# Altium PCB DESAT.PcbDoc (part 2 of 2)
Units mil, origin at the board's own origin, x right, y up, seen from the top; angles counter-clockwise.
Board outline 3543.31 x 1895 mil, 4 copper layers (Top Layer, Signal Layer 1, Signal Layer 2, Bottom Layer), stack 40 mil thick; 82 components, 118 nets, 154 pads, 24 vias.
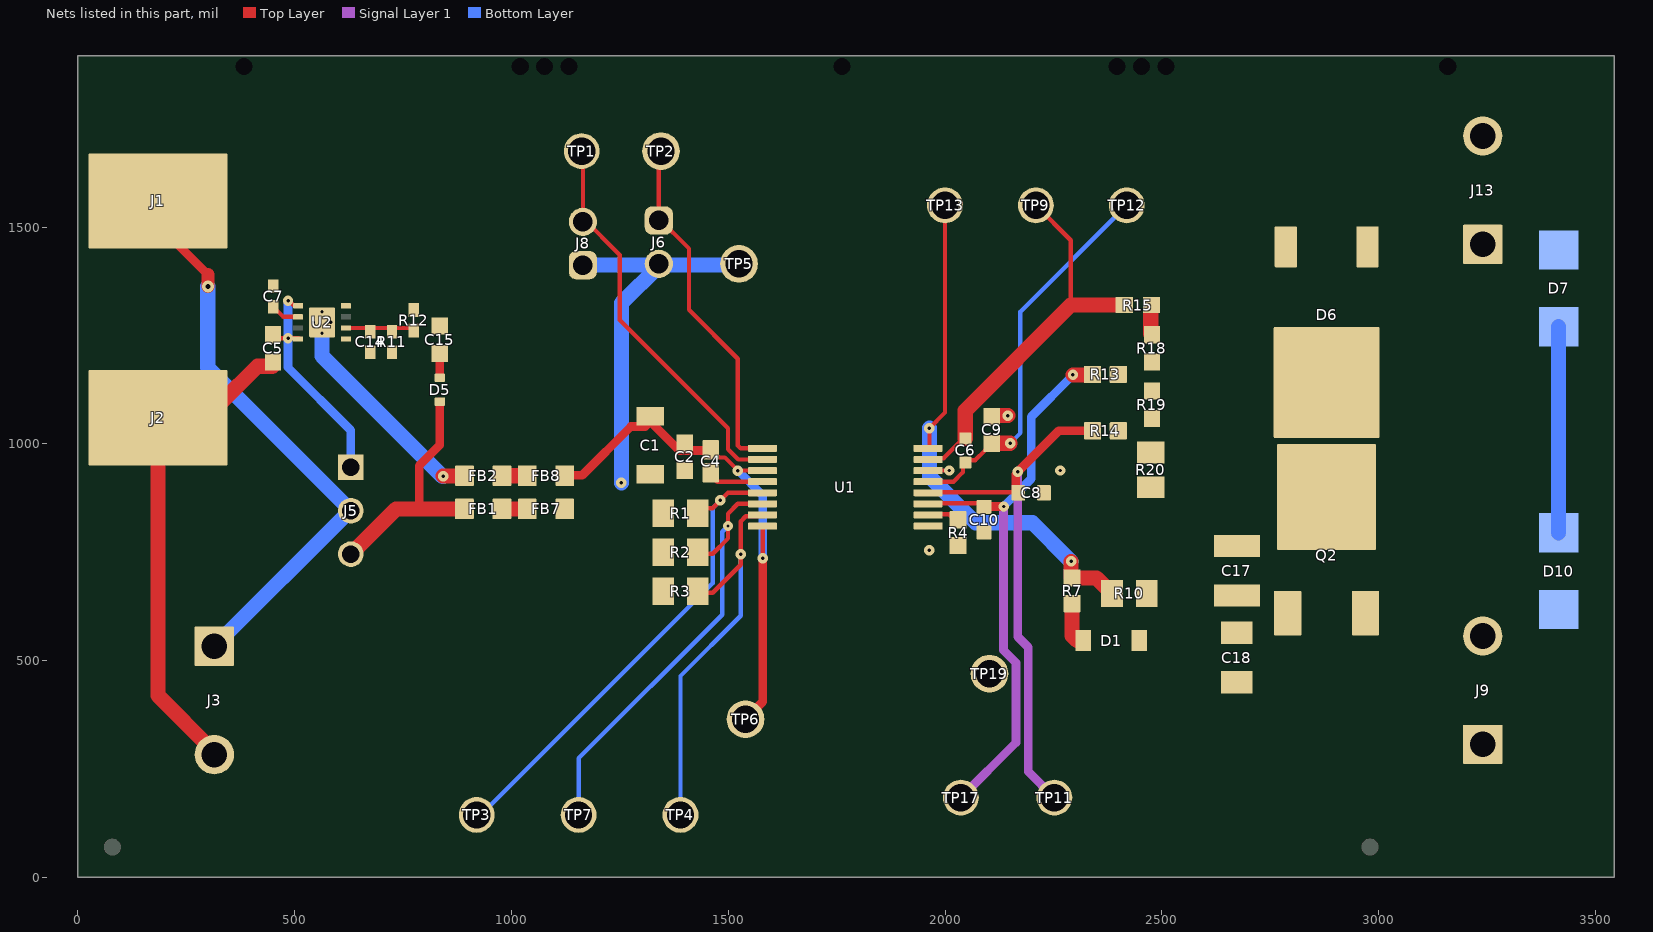
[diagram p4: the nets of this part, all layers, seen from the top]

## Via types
v1: diameter 24, hole 8, Top Layer to Bottom Layer, tented both sides, 19 vias
v2: diameter 19.68, hole 7.87, Top Layer to Bottom Layer, 4 vias
v3: diameter 27.56, hole 11.81, Top Layer to Bottom Layer, tented both sides, 1 vias

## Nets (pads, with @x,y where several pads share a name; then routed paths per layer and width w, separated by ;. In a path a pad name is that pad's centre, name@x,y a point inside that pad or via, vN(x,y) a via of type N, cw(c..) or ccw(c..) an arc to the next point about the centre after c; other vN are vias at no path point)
1ALM1_CMP: 
1CE: 
1EN: 
1FLT1_CMP: 
1HV+: 
1LDO_IN+: 
1LDO_OUT: 
1nALM1: 
1nFLT1: 
1PGOOD: 
1RESP: 
1VDDH: 
1VDDM: 
1VDDP: 
1VDDP_filtered: 
1VDRV: 
1VGATE: 
1VSSP: 
1VSSP_filtered: 
1VSSS: 
2CE: 
2EN: 
2FLT1_CMP: 
2FLT2_CMP: 
2HV+: 
2HV-: 
2LDO_IN+: 
2LDO_OUT: 
2nFLT1: 
2nFLT2: 
2PGOOD: 
2RESP: 
2VDDH: 
2VDDM: 
2VDDP: 
2VDDP_filtered: 
2VDRV: 
2VGATE1: 
2VGATE2: 
2VSSP: 
2VSSP_filtered: 
2VSSS: 
3ALM1_CMP: 
3CE: 
3EN: 
3FLT1_CMP: 
3HV+: 
3IN+: 
3LDO_IN+: 
3LDO_OUT: 
3nALM1: 
3nFLT1: 
3PGOOD: 
3RESP: 
3VDDH: 
3VDDM: 
3VDDP: 
3VDDP_filtered: 
3VDRV: 
3VGATE: 
3VSSP: 
3VSSP_filtered: 
3VSSS: 
4ALM1_CMP: C10.2 R13.1 TP17.1 U1.11 | length 1338.9
  Top Layer w10: U1.11@1951.57,862.87 2083.26,862.87 C10.2@2090.62,855.51
  Top Layer w20: C10.2@2090,854.53 2090.98,855.51 v1(2134.98,855.51)
  Top Layer w35: v1(2295.06,1158.98) 2339.23,1158.98 R13.1@2340.28,1160.02
  Signal Layer 1 w20: TP17.1@2036.59,184.16 2163.87,311.45 2163.87,495.42 2134.98,524.31 v1(2134.98,855.51)
  Bottom Layer w20: v1(2134.98,855.51) 2198.68,919.2 2198.68,1062.59 v1(2295.06,1158.98)
4CE: J8.2 TP1.1 U1.2 | length 928
  Top Layer w10: TP1.1@1165,1687.75 1165,1520.54 1250,1435.54 1250,1285.7 1499.54,1036.16 1499.54,987.64 1523.2,963.98 U1.2@1579.06,963.98
4EN: J6.1 TP2.1 U1.1 | length 828.6
  Top Layer w10: TP2.1@1340,1689.72 1340,1519.72 1409.46,1450.26 1409.46,1309.07 1522.17,1196.36 1522.17,996.26 1528.86,989.57 U1.1@1579.06,989.57
4FLT1_CMP: C8.2 R14.1 TP11.1 U1.12 | length 1258.8
  Top Layer w10: U1.12@1951.57,888.46 C8.2@2159.55,888.46
  Top Layer w20: C8.2@2169.15,886.99 2163.4,892.73 2163.4,930.14 2167.79,934.54 v1(2167.79,935.62) 2262.17,1030 R14.1@2340.28,1030
  Signal Layer 1 w20: v1(2167.79,935.62) 2167.79,554.87 2191.74,530.92 2191.74,244.52 TP11.1@2252.1,184.16
4HV+: D6.1 D7.1 J13.1 J13.2
4LDO_IN+: C5.1 J5.1 U2.5 U2.8 | length 532
  Top Layer w10: C5.1@449.96,1244.2 450.62,1243.54 v1(485,1243.54) U2.8@509.76,1243.54 ; v1(485,1329.72) 487.62,1329.72 497.86,1319.49 507.16,1319.49 U2.5@508.26,1318.39
  Bottom Layer w20: v1(485,1329.72) 485,1176.29 629.87,1031.42 J5.1@629.87,945.72
4LDO_OUT: C14.1 C15.1 D5.2 R11.2 U2.1 | length 57.2
  Top Layer w20: D5.2@835,1152.34 C15.1@835,1208.5 C15.1@835.72,1207.78
4nALM1: R3.2 TP4.1 U1.7 | length 956.5
  Top Layer w10: R3.2@1430,654.72 1431.78,656.5 1464.14,656.5 1528.86,721.22 v1(1528.86,745.72) 1528.86,821.14 1540.67,832.95 1581.29,832.95 U1.7@1584.36,836.02
  Bottom Layer w10: TP4.1@1390,134.72 1390,464.72 1528.86,603.58 v1(1528.86,745.72)
4nFLT1: R2.2 TP7.1 U1.6 | length 1054.6
  Top Layer w10: R2.2@1430,744.72 1431.92,746.65 1464.14,746.65 1499.54,782.04 v1(1499.54,810.51) 1499.54,838.98 1522.17,861.61 U1.6@1584.36,861.61
  Bottom Layer w10: TP7.1@1155,134.72 1155,274.72 1486.17,605.9 1486.17,797.15 v1(1499.54,810.51)
4PGOOD: R1.2 TP3.1 U1.5 | length 1143.6
  Top Layer w10: R1.2@1430,834.72 1447.09,851.81 1464.14,851.81 v1(1481.84,869.51) 1499.54,887.2 U1.5@1584.36,887.2
  Bottom Layer w10: TP3.1@920,134.72 1464,678.72 1464,851.67 v1(1481.84,869.51)
4RESP: R4.1 U1.10 | length 88
  Top Layer w10: U1.10@1951.57,837.28 2009.05,837.28 R4.1@2030.62,815.71
4VDDH: C6.1 R15.2 TP9.1 U1.15 | length 899.2
  Top Layer w10: U1.15@1960.95,963.98 1964.02,967.05 1997.03,967.05 2033.48,1003.5 2038.01,1003.5 C6.1@2046.79,1012.28 ; TP9.1@2209.59,1550 2289.92,1469.67 2289.92,1320
  Top Layer w35: C6.1@2046.79,1012.28 2046.79,1076.88 2289.92,1320 R15.2@2411.58,1320
4VDDM: C6.2 C9.2 TP12.1 U1.13 | length 895.8
  Top Layer w10: U1.13@1960.95,912.8 2019.51,912.8 2041.51,934.8 2041.51,951.87 2051.84,962.21 2069.38,962.21 2093.03,985.85 2094.02,985.85 C9.2@2107.72,999.55
  Top Layer w35: C9.2@2107.72,999.55 2109.66,1001.5 v1(2150,1001.5)
  Bottom Layer w10: v1(2150,1001.5) 2173.79,1025.29 2173.79,1304.62 TP12.1@2419.17,1550
4VDDP: D5.1 FB1.1 J5.3 | length 577.1
  Top Layer w20: 775,850 787.5,862.5 787.5,949.81 835,997.31 D5.1@835,1097.22
  Top Layer w35: J5.3@629.87,745.72 734.15,850 775,850 787.5,850 FB1.1@891.69,850
4VDDP_filtered: C1.1 C2.1 C4.2 FB7.2 J6.2 J8.1 R1.1 R2.1 R3.1 TP5.1 U1.4 | length 1008
  Top Layer w10: C4.2@1460,927.37 1474.58,912.79 U1.4@1579.06,912.8
  Bottom Layer w35: J8.1@1166.17,1412.11 TP5.1@1511.17,1412.11 ; v1@1254.29,909.36 1254.29,1324.41 J6.2@1341.17,1411.29
  other v1: 1253.52,910.32
4VDRV: R7.1 R10.1 TP13.1 U1.16 | length 1245.6
  Top Layer w10: U1.16@1960.95,989.57 1964.02,992.64 v1(1964.02,1036.16) 2000,1072.14 TP13.1@2000,1550
  Top Layer w35: v1(2290.86,728.83) 2290.86,693.11 R7.1@2293.1,690.87 2349.13,690.87 2371,669 2377.5,669 2385,661.5 R10.1@2385,655
  Bottom Layer w35: v1(1964.02,1036.16) 1964.02,924.52 2070.4,818.14 2201.55,818.14 v1(2290.86,728.83)
4VGATE: C17.2 C18.2 D1.2 Q2.1 R10.2
4VSSP: C5.2 C7.2 C15.2 FB2.1 J2.1 J3.2 R12.1 U2.4 U2.9 | length 1593.2
  Top Layer w35: J3.2@309.86,294.49 185,419.36 185,1004.72 277.5,1097.22 332.5,1097.22 414.3,1179.02 448.76,1179.02 449.96,1180.22 C5.2@449.96,1181.21 ; v1(842.65,925.67) 886.76,925.67 FB2.1@888.46,927.37
  Bottom Layer w35: v2(563.38,1255.39) 563.38,1202.77 v1@841.56,924.58
  other v2: 543.69,1280 583.06,1280 563.38,1304.61
4VSSP_filtered: C1.2 C2.2 C4.1 FB8.2 TP6.1 U1.3 U1.8 | length 1250.4
  Top Layer w10: C4.1@1460,986.6 1460,983.3 1473.86,969.44 1479.02,969.44 1480.02,968.44 1492.43,968.44 v1(1522.48,938.39) U1.3@1579.06,938.39 ; U1.8@1579.06,810.43 1580,809.49 v1(1580,735.96)
  Top Layer w20: FB8.2@1120.08,927.37 1163.14,927.37 1275.92,1040.16 1308.5,1040.16 1320,1051.65 1386.94,984.72 1455.86,984.72 C4.1@1460,980.58 ; TP6.1@1540,365 1580,405 v1(1580,735.96)
  Bottom Layer w20: v1(1522.48,938.39) 1580,880.87 v1(1580,735.96)
4VSSS: C8.1 C9.1 C10.1 C18.1 D10.2 J9.1 J9.2 Q2.3 R4.2 R20.1 TP19.1 U1.9 U1.14 | length 87
  Top Layer w10: U1.14@1960.95,938.39 2009.92,938.39 v1(2010.04,938.5)
  Top Layer w35: C9.1@2107.72,1063.53 2109.19,1065 v1(2145,1065)
  other v1: 1964.02,755 2265.5,938.5
NetC7_1: C7.1 U2.6 | length 67.4
  Top Layer w10: C7.1@450.62,1316.42 474.24,1292.8 U2.6@508.26,1292.8
NetC11_2: 
NetC13_1: 
NetC14_2: C14.2 R11.1 R12.2 U2.2 | length 158.9
  Top Layer w10: U2.2@618.49,1267.2 769.17,1267.2 R12.2@775,1261.38
NetC17_1: C17.1 D6.3 Q2.2
NetC30_2: 
NetC32_1: 
NetC47_1: 
NetC51_2: 
NetC53_1: 
NetD1_1: D1.1 R7.2 | length 89.9
  Top Layer w35: R7.2@2293.1,631.42 2293.1,557.4 D1.1@2304.36,546.14
NetD2_1: 
NetD3_1: 
NetD4_1: 
NetD6_2: D6.2 R15.1 R18.2 | length 69.5
  Top Layer w35: R15.1@2474.57,1320 2474.57,1254 R18.2@2477.12,1251.5
NetD7_2: D7.2 D10.1 | length 475
  Bottom Layer w35: D10.1@3415,795 D7.2@3415,1270
NetD11_1: 
NetD13_2: 
NetD15_1: 
NetD17_2: 
NetFB1_2: FB1.2 FB7.1 | length 58.4
  Top Layer w35: FB1.2@978.31,850 FB7.1@1036.69,850
NetFB2_2: FB2.2 FB8.1 | length 58.4
  Top Layer w35: FB2.2@978.31,926.56 FB8.1@1036.69,926.56
NetFB3_2: 
NetFB4_2: 
NetFB5_2: 
NetFB6_2: 
NetFB9_2: 
NetFB10_2: 
NetJ1_1: J1.1 J3.1 J5.2 | length 1279.9
  Top Layer w20: J1.1@185,1490.55 200,1490.55 300,1390.55
  Top Layer w30: v3(300,1362.74) 300,1390.55
  Bottom Layer w35: v3(300,1362.74) 300,1175.59 J5.2@629.87,845.72 ; J3.1@314.96,533.19 J5.2@627.49,845.72
NetJ4_1: 
NetJ15_1: 
NetJ19_1: 
NetR13_2: R13.2 R18.1 R19.2
NetR14_2: R14.2 R19.1 R20.2
NetR47_2: 
pads on no net: FID1.1 FID2.1 H5.0 H6.0 H7.0 H8.0 SH-J1.0 SH-J2.0 SH-J3.0 SH-J4.0 SH-J5.0 SH-J6.0 SH-J9.0 SH-J10.0 SH-J11.0 SH-J12.0 U2.3 U2.7

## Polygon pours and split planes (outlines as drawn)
4VSSS on Top Layer "Top Layer-4VSSS" (solid, remove dead copper, pour order 52): 1930,115 2025,20 3062,20 3543.31,20 3543.31,475 3530,475 3530,662.5 2940,662.5 2940,565.32 2849.68,475 2247.51,475 2177.76,544.75 2177.76,691.48 2231,744.72 2369.48,744.72 2505.62,880.87 2504.34,882.14 2504.34,927.5 2275.27,1156.58 2000,1156.58 1928.23,1084.81 1928.23,744.72 1930,744.72
4VSSP on Top Layer "TOP_LAYER_4VSSP_P025" (solid, remove dead copper, pour order 25): 429.46,1160.97 543.34,1160.97 631.81,1249.45 855.67,1249.45 863.54,1257.32 863.54,1346.18 830.42,1379.31 429.46,1379.31
4VDDP_filtered on Top Layer "TOP_LAYER_4VDDP_FILTERED_P023" (solid, remove dead copper, pour order 23): 1100.36,872.07 1100.36,830.96 1290.36,640.96 1290.36,622.07 1373.09,622.07 1373.09,872.07 1411.81,910.79 1472.85,910.79 1472.85,955.33 1237.31,955.33 1154.05,872.07
NetD6_2 on Top Layer "TOP_LAYER_NETD6_2_P073" (solid, remove dead copper, pour order 73): 2807.87,1405 2669.45,1405 2499.45,1235 2454.79,1235 2454.79,1337.7 2622.08,1505 2807.87,1505
4HV+ on Top Layer "TOP_LAYER_4HV+_P072" (solid, remove dead copper, pour order 72): 2950,1405 2950,1780 3012.87,1842.87 3543.31,1842.87 3540,1839.57 3540,1405
4VGATE on Top Layer "TOP_LAYER_4VGATE_P059" (solid, remove dead copper, pour order 59): 2421.9,505 2609.35,505 2637.49,533.14 2795.74,533.14 2820,557.4 2820,661.15 2737.11,661.15 2726.07,672.19 2514.57,672.19 2499.45,687.31 2443.08,687.31 2425,669.23 2425,587.59 2421.9,584.5
NetC17_1 on Top Layer "TOP_LAYER_NETC17_1_P043" (solid, remove dead copper, pour order 43): 2619.77,740 2973.05,740 3000.01,766.95 3000.01,853.52 2774.47,853.52 2712.48,791.54 2620.32,791.54
NetR14_2 on Top Layer "TOP_LAYER_NETR14_2_P041" (solid, remove dead copper, pour order 41): 2406.93,1075.62 2379.4,1048.1 2380.44,1047.06 2380.44,1008.18 2434.12,954.5 2505.62,954.5 2505.62,1059.42 2489.42,1075.62
NetR13_2 on Top Layer "TOP_LAYER_NETR13_2_P040" (solid, remove dead copper, pour order 40): 2409.58,1207.5 2382.06,1179.98 2383.1,1178.94 2383.1,1140.06 2416.48,1106.68 2493.1,1106.68 2493.1,1206.48 2492.07,1207.5
4LDO_OUT on Top Layer "TOP_LAYER_4LDO_OUT_P024" (solid, remove dead copper, pour order 24): 609.86,1249.45 639.67,1249.45 654.4,1234.72 759.52,1234.72 763,1231.24 850,1231.24 850,1189.22 639.87,1189.22 609.86,1219.23
NetC17_1 on Top Layer "TOP_LAYER_NETC17_1_P005" (solid, remove dead copper, pour order 5): 2756.49,755 2756.49,1270 3000.01,1270 3000.01,755
4VSSS on Bottom Layer "Bottom Layer-4VSSS" (solid, remove dead copper, pour order 51): 1930,115 2025,20 3062,20 3543.31,20 3543.31,475 3530,475 3530,662.5 2940,662.5 2940,565.32 2849.68,475 2247.51,475 2177.76,544.75 2177.76,691.48 2231,744.72 2369.48,744.72 2505.62,880.87 2504.34,882.14 2504.34,927.5 2275.27,1156.58 2000,1156.58 1928.23,1084.81 1928.23,744.72 1930,744.72
4HV+ on Bottom Layer "BOTTOM_LAYER_4HV+_P087" (solid, remove dead copper, pour order 87): 2950,1405 2950,1780 3012.87,1842.87 3543.31,1842.87 3540,1839.57 3540,1405
4VSSS on Signal Layer 1 "Signal Layer 1-4VSSS" (solid, remove dead copper, pour order 53): 1930,115 2025,20 3062,20 3543.31,20 3543.31,475 3530,475 3530,662.5 2940,662.5 2940,565.32 2849.68,475 2247.51,475 2177.76,544.75 2177.76,691.48 2231,744.72 2369.48,744.72 2505.62,880.87 2504.34,882.14 2504.34,927.5 2275.27,1156.58 2000,1156.58 1928.23,1084.81 1928.23,744.72 1930,744.72
4HV+ on Signal Layer 1 "SIGNAL_LAYER_1_4HV+_P102" (solid, remove dead copper, pour order 102): 2950,1405 2950,1780 3012.87,1842.87 3543.31,1842.87 3540,1839.57 3540,1405
4HV+ on Signal Layer 2 "SIGNAL_LAYER_2_4HV+_P038" (solid, remove dead copper, pour order 38): 2950,1405 2950,1780 3012.87,1842.87 3543.31,1842.87 3540,1839.57 3540,1405
4VSSS on Signal Layer 2 "Signal Layer 2-4VSSS" (solid, remove dead copper, pour order 54): 1930,115 2025,20 3062,20 3543.31,20 3543.31,475 3530,475 3530,662.5 2940,662.5 2940,565.32 2849.68,475 2247.51,475 2177.76,544.75 2177.76,691.48 2231,744.72 2369.48,744.72 2505.62,880.87 2504.34,882.14 2504.34,927.5 2275.27,1156.58 2000,1156.58 1928.23,1084.81 1928.23,744.72 1930,744.72

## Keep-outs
Keep-Out Layer:
  text ".Layer_Name" at 577,-858.49 h60

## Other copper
Top Layer:
  text ".Layer_Name" at 577,-858.49 h60
Bottom Layer:
  text ".Layer_Name" at 577,-858.49 h60

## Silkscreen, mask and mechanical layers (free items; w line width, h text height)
Top Overlay:
  rectangle: 6627.17,6843.78 6927.17,6943.78
  lines w6: 1169.99,1348.56 1201.07,1317.48 1204.24,1317.48 1316,1317.48 1339.48,1294 ; 1340,1351.72 1340,1294 1339.48,1294 ; 1510,1331.19 1494.71,1315.9 1361.38,1315.9 1339.48,1294
  lines w10: 1632.2,70 1632.2,110 ; 1632.2,150 1632.2,190 ; 1632.2,230 1632.2,270 ; 1632.2,310 1632.2,350 ; 1632.2,390 1632.2,430 ; 1632.2,470 1632.2,510 ; 1632.2,550 1632.2,590 ; 1632.2,630 1632.2,670 ; 1632.2,1110 1632.2,1150 ; 1632.2,1190 1632.2,1230 ; 1632.2,1270 1632.2,1310 ; 1632.2,1350 1632.2,1390 ; 1632.2,1430 1632.2,1470 ; 1632.2,1510 1632.2,1550 ; 1632.2,1590 1632.2,1630 ; 1632.2,1670 1632.2,1710 ; 1632.2,1750 1632.2,1790 ; 1909.43,70 1909.43,110 ; 1909.43,150 1909.43,190 ; 1909.43,230 1909.43,270 ; 1909.43,310 1909.43,350 ; 1909.43,390 1909.43,430 ; 1909.43,470 1909.43,510 ; 1909.43,550 1909.43,590 ; 1909.43,630 1909.43,670 ; 1909.43,1110 1909.43,1150 ; 1909.43,1190 1909.43,1230 ; 1909.43,1270 1909.43,1310 ; 1909.43,1350 1909.43,1390 ; 1909.43,1430 1909.43,1470 ; 1909.43,1510 1909.43,1550 ; 1909.43,1590 1909.43,1630 ; 1909.43,1670 1909.43,1710 ; 1909.43,1750 1909.43,1790
  text "DESAT" at 577.76,1774.65 h100
  text "CE" at 1147.5,1767.72 h30
  text "EN" at 1317.5,1767.72 h30
  text "VDDH" at 2149.57,1645.33 h30
  text "VDDM" at 2359.62,1645.33 h30
  text "VDRV" at 1934.23,1641.85 h30
  text "+" at 355,1536.08 h90
  text "VDDP" at 1288.6,1251.35 h30
  text "HV+" at 3245,1225.25 h90
  text "-" at 367.13,1036.37 h90
  text "LDO" at 731.32,935.98 h30
  text "+" at 525.73,829.51 h30
  text "Device" at 725.51,729.89 h30
  text "VSSS" at 3235.33,723.23 h90
  text "TPSI3133-Q1" at 1620.82,720 h30
  text "VSSS" at 2039.55,559.87 h30
  text "+" at 512.13,516.08 h90
  text "-" at 522.13,264.34 h90
  text "VSSP" at 1485.63,249.36 h30
  text "Max DC Load: / 600-V / 5-A" at 2565,78.68 h40
  text "ALM-CMP" at 1930.01,71.6 h30
  text "FLT-CMP" at 2165.55,71.6 h30
  text "PGOOD" at 860.05,23.15 h30
  text "nFLT" at 1101.94,23.15 h30
  text "nALM" at 1342.59,23.15 h30
  text ".Layer_Name" at 577,-858.49 h60
Bottom Overlay:
  text ".Layer_Name" at 577,-858.49 h60
Top Paste:
  text ".Layer_Name" at 577,-858.49 h60
Bottom Paste:
  text ".Layer_Name" at 577,-858.49 h60
Top Solder:
  text ".Layer_Name" at 577,-858.49 h60
  text ".Layer_Name" at 577,-858.49 h60
Bottom Solder:
  text ".Layer_Name" at 577,-858.49 h60
Drill Guide:
  text ".Layer_Name" at 577,-858.49 h60
M1 Board Outline:
  lines w10: 0,0 3543.31,0
  text ".Layer_Name" at 577,-858.49 h60
M2 Board Dimensions:
  rectangle: 0,-275 125,-150
  rectangle: 125,-400 500,-275
  lines w7: 0,-275 1000,-275 ; 125,-400 125,-150 ; 250,-400 250,-150 ; 500,-400 500,-150 ; 750,-400 750,-150 ; 0,-400 1000,-400 1000,-150 0,-150 0,-400
  text ".Layer_Name" at 577,-858.49 h60
M3 3D STEP Top:
  text ".Layer_Name" at 577,-858.49 h60
M4 3D STEP Bottom:
  text ".Layer_Name" at 577,-858.49 h60
M5 Assembly Top:
  lines w10: -292,-930.17 6308,-930.17 ; -292,-726.83 6310,-726.83 ; -292,-523.5 -292,-1133.5 3713,-1133.5 6310,-1133.5 6310,-523.5 -291.5,-523.5 -291.5,-1133.5 1284,-1133.5 ; 2173,-1133.5 2173,-523.5 ; 3440,-726.83 3440,-523.5 ; 4280,-726.83 4280,-523.5 ; 4902,-1140 4902,-937.17
  text "COMPONENTS MARKED 'DNP' SHOULD NOT BE POPULATED." at 1153.5,-318.5 h60
  text "ASSEMBLY VARIANT:" at 1153,-434 h60
  text ".VariantName" at 2189,-434 h60
  text "PCB VIEWED FROM TOP SIDE" at -228.5,-655.67 h60
  text "BOARD #:" at 2248,-655.67 h60
  text ".PRJ_Number" at 2793.5,-655.67 h60
  text "REV:" at 3638,-655.67 h60
  text ".PCB_Rev" at 3929.5,-655.67 h60
  text "SVN REV:" at 4476,-655.67 h60
  text ".VersionControl_RevNumber" at 4982,-655.67 h60
  text "TID #:" at 2248,-859 h60
  text ".TID" at 2793.5,-859 h60
  text "PLOT NAME =" at -228.5,-1064.34 h60
  text ".plot_File_Name" at 577,-1064.34 h60
  text "GENERATED    :" at 2250,-1064.34 h60
  text ".Print_Date" at 3119.5,-1064.34 h60
  text ".Print_Time" at 3848.5,-1064.34 h60
  text "TEXAS INSTRUMENTS" at 5113,-1064.34 h60
M6 Assembly Bottom:
  lines w10: -292.5,-727.33 6309.5,-727.33 ; -290.5,-930.67 6309.5,-930.67 ; 1115.5,-1140.5 1115.5,-937.67 ; 1737.5,-727.33 1737.5,-524 ; 2577.5,-727.33 2577.5,-524 ; 3844.5,-1134 3844.5,-524 ; 4733.5,-1134 6309,-1134 6309,-524 -292.5,-524 -292.5,-1134 2304.5,-1134 6309.5,-1134 6309.5,-524
  text "COMPONENTS MARKED 'DNP' SHOULD NOT BE POPULATED." at 6102,-318 h60
  text ".VariantName" at 5058,-434 h60
  text "ASSEMBLY VARIANT:" at 6097,-434 h60
  text ".VersionControl_RevNumber" at 1035.5,-656.17 h60
  text "SVN REV:" at 1541.5,-656.17 h60
  text ".PCB_Rev" at 2088,-656.17 h60
  text "REV:" at 2379.5,-656.17 h60
  text ".PRJ_Number" at 3224,-656.17 h60
  text "BOARD #:" at 3769.5,-656.17 h60
  text "PCB VIEWED FROM BOTTOM SIDE" at 6246,-656.17 h60
  text ".TID" at 3224,-859.5 h60
  text "TID #:" at 3769.5,-859.5 h60
  text "TEXAS INSTRUMENTS" at 904.5,-1064.84 h60
  text ".Print_Time" at 2169,-1064.84 h60
  text ".Print_Date" at 2898,-1064.84 h60
  text "GENERATED    :" at 3767.5,-1064.84 h60
  text ".plot_File_Name" at 5440.5,-1064.84 h60
  text "PLOT NAME =" at 6246,-1064.84 h60
M9 Title Sheet:
  drawing of 57 lines, arcs and shapes, not listed
  text "1" at 739.84,8036.5 h70
  text "2" at 3235.5,8036.5 h70
  text "3" at 5724.84,8036.5 h70
  text "4" at 8231.51,8036.5 h70
  text "5" at 10730.5,8036.5 h70
  text "6" at 13235.5,8036.5 h70
  text "A" at -416.5,6893.5 h70
  text "A" at 14383.5,6893.5 h70
  text "B" at -416.5,4513.5 h70
  text "B" at 14383.5,4513.5 h70
  text "C" at -416.5,2138.5 h70
  text "C" at 14383.5,2138.5 h70
  text "PROJECT TITLE:" at 11343.5,277.5 h45
  text ".PRJ_Title" at 11393.5,144.17 h70
  text "DESIGNED FOR:" at 11343.5,-23.5 h45
  text ".PRJ_Customer" at 11393.5,-163.5 h70
  text "D" at -416.5,-231.5 h70
  text "D" at 14383.5,-231.5 h70
  text "FILE NAME:" at 11343.5,-323.5 h45
  text ".PCB_File_Name_No_Path" at 11393.5,-443.5 h70
  text "Texas Instruments (TI) and/or its licensors do not warrant the accuracy or completeness of this specification" at 6374,-605.34 h45
  text "ENGINEER:" at 11343.5,-613.5 h45
  text "LAYOUT BY:" at 12848.5,-613.5 h45
  text "or any information contained therein. TI and/or its licensors do not warrant that this design will meet" at 6329.01,-718 h45
  text ".PRJ_Engineer" at 11393.5,-768.49 h70
  text ".PCB_Layout" at 12899,-768.49 h70
  text "the specifications, will be suitable for your application or fit for any particular purpose, or will operate in" at 6329.01,-830.67 h45
  text ".Layer_Name" at 577,-858.49 h60
  text "ALTIUM DESIGNER VERSION:" at 12848.5,-923.5 h45
  text "an implementation. TI and/or its licensors do not warrant that the design is production worthy. You should" at 6329.01,-943.33 h45
  text "completely validate and test your design implementation to confirm the system functionality for your application." at 6374,-1056 h45
  text ".print_Scale" at 11393.5,-1056.83 h70
  text ".Application_BuildNumber" at 12899,-1056.83 h70
  text "1" at 739.84,-1263.5 h70
  text "2" at 3235.5,-1263.5 h70
  text "3" at 5724.84,-1263.5 h70
  text "4" at 8231.51,-1263.5 h70
  text "5" at 10730.5,-1263.5 h70
  text "6" at 13235.5,-1263.5 h70
M10 Fab Notes:
  drawing of 189 lines, arcs and shapes, not listed
  text "DESIGN INFORMATION" at 12382.02,6356.17 h60
  text "MIN. TRACK WIDTH:" at 11737.46,6224.05 h60
  text "8" at 12833.7,6224.05 h60
  text "MIL" at 12988.46,6224.05 h60
  text "7.874" at 12667.32,6102.36 h60
  text "MIN. CLEARANCE:" at 11737.46,6099.92 h60
  text "MIL" at 12988.46,6099.92 h60
  text "MIN. VIA PAD SIZE:" at 11737.46,5975.8 h60
  text "24" at 12803.71,5975.8 h60
  text "MIL" at 12988.46,5975.8 h60
  text "0.05mm (2MIL)" at 12432.46,5845.9 h60
  text "MINIMUM ANNULAR RING" at 11408.23,5837.67 h60
  text "EXTERNAL" at 13140.46,5837.67 h60
  text "PER" at 11608.23,5727.55 h60
  text "IPC-D-275 CLASS 2 LEVEL C" at 11828.23,5727.54 h60
  text "MIL, HOLES" at 13316.46,5627.07 h60
  text "+/-" at 12924,5618.48 h60
  text "+/-" at 13778,5618.48 h60
  text "REGISTRATION TOLERANCES:" at 11408.23,5617.42 h60
  text "METAL" at 12608,5617.42 h60
  text "5" at 13184.2,5617.42 h60
  text "3" at 14017.2,5617.42 h60
  text "MIL" at 14133.46,5617.42 h60
  text "HOLE SIZE TOLERANCE (UNLESS OTHERWISE SPECIFIED):" at 11408.23,5519.1 h60
  text "+/-" at 13778,5516.23 h60
  text "3" at 14017.2,5515.17 h60
  text "MIL" at 14133.46,5515.17 h60
  text "MATERIAL:" at 11333.46,5377.52 h60
  text "FR-4 High Tg" at 12319.9,5249 h60
  text "X" at 12175.46,5241.01 h60
  text "FR-4" at 11754.46,5236.49 h60
  text "OTHER" at 13242.46,5236.49 h60
  text "62 MIL (1.6mm) +/-10%" at 12074.56,5093.46 h60
  text "X" at 11954.46,5091.01 h60
  text "THICKNESS:" at 11408.23,5085.24 h60
  text "OTHER" at 13359.46,5085.24 h60
  text "TOLERANCE:" at 11408.23,4946.92 h60
  text "X" at 12256.46,4946.92 h60
  text "ANSI IPC-6012 TYPE 3 CLASS 2" at 12434.48,4946.92 h60
  text "OTHER +/-" at 12434.46,4802.73 h60
  text "BOW & TWIST:" at 11408.23,4657.54 h60
  text "X" at 12256.46,4657.54 h60
  text "ANSI IPC-6012 TYPE 3 CLASS 2" at 12434.48,4657.54 h60
  text "OTHER +/-" at 12434.46,4510.85 h60
  text "DRILLING:" at 11333.46,4380.23 h60
  text "NC_DRILL FILES" at 13094.46,4275.04 h60
  text "REFERENCE:" at 11408.23,4271.1 h60
  text "X" at 12065.46,4271.01 h60
  text "AS SHOWN" at 12243.46,4271.1 h60
  text "X" at 12966.46,4271.1 h60
  text "OTHER" at 13392.46,4128.85 h60
  text "PTH COPPER THICKNESS:" at 11407.91,4125.32 h60
  text "X" at 12547.14,4125.32 h60
  text "20-30 um" at 12675.14,4125.32 h60
  text "BOARD FINISH:" at 11333.46,3977.73 h60
  text "SILKSCREEN:" at 11488.68,3867.6 h60
  text "X" at 12446.46,3867.6 h60
  text "TOP" at 12563.46,3867.6 h60
  text "X" at 12956.46,3867.6 h60
  text "BOTTOM" at 13074.46,3867.6 h60
  text "SILKSCREEN COLOR:" at 11488.68,3712.41 h60
  text "X" at 12445.46,3712.41 h60
  text "WHITE" at 12563.46,3712.41 h60
  text "OTHER" at 13074.46,3712.41 h60
  text "X" at 12576.46,3568.96 h60
  text "GREEN" at 12694.46,3568.96 h60
  text "OTHER" at 13312.46,3568.96 h60
  text "SOLDER RESIST COLOR:" at 11488.68,3562.1 h60
  text "X" at 12576.46,3414.71 h60
  text "MATTE" at 12694.46,3414.71 h60
  text "SEMI-GLOSS" at 13312,3414.07 h60
  text "IMMERSION GOLD (ENIG)" at 12394.46,3241.94 h60
  text "ENEPIG" at 13732,3234.72 h60
  text "SURFACE FINISH:" at 11333.46,3233.72 h60
  text "X" at 12216.46,3233.72 h60
  text "IMM. TIN/SILVER OR EQUIV" at 11663,3096.4 h60
  text "OTHER" at 13094.46,3092.47 h60
  text "ARRAY/PANEL:" at 11333.46,2937.09 h60
  text "CUT AND TRIM PER M1 BOARD OUTLINE" at 12394.46,2928.87 h60
  text "N.C. ROUTE" at 12394.46,2792.9 h60
  text "X" at 13082.46,2792.9 h60
  text "V. SCORE" at 13260.46,2792.9 h60
  text "CERTIFICATION:" at 11333.46,2663.77 h60
  text "MATERIALS AND WORKMANSHIP FOR ALL PCBS" at 12058.46,2663.77 h60
  text "TO MEET OR EXCEED THE REQUIREMENTS OF:" at 12058.46,2569.71 h60
  text "X" at 11695.97,2441.08 h60
  text "ANSI IPC-A-600F CLASS ->" at 11823.96,2441.08 h60
  text "X" at 13471.97,2441.08 h60
  text "2" at 13581.96,2441.08 h60
  text "1" at 13266.96,2439.58 h60
  text "3" at 13935.96,2439.58 h60
  text "X" at 12507.97,2293.39 h60
  text "RoHS" at 12635.96,2293.39 h60
  text "OTHER" at 13280.36,2293.39 h60
  text "PER ORDER" at 13677.42,2293.39 h60
  text "ALL BOARDS MUST MEET OR EXCEED UL94-V0 REQUIREMENTS." at 11361,2139.57 h60
  text "PCB MUST BEAR THE UL94V-0 UL REGISTERED MATERIAL ID NUMBER" at 11361,2023.5 h60
  text "ADDITIONAL REQUIREMENTS:" at 11333.46,1854.08 h60
  text "MICROSECTION:" at 11408.23,1746.95 h60
  text "YES" at 12313.96,1746.95 h60
  text "REQUIRED" at 13175.46,1602.62 h60
  text "BARE BOARD ELEC. TEST:" at 11408.23,1599.76 h60
  text "NONE" at 12713.96,1599.76 h60
  text "X" at 13057.46,1599.76 h60
  text "PER ORDER" at 13767.46,1599.76 h60
  text "XX MIL VIAS REQUIRE NON-CONDUCTIVE FILL AND PLANARIZE" at 11576.38,1394.82 h59
  text "XX MIL VIAS REQUIRE CONDUCTIVE FILL AND PLANARIZE" at 11584.38,1290.84 h60
  text "OUTER XX MIL TRACES REQUIRE 50 OHM SINGLE-ENDED IMPEDANCE" at 11583.39,1127.46 h58
  text "LAYER 2 & 3 (INNER LAYERS) XX MIL WIDE, XX MIL SPACE / TRACES REQUIRE 100 OHM DIFFERENTIAL IMPEDANCE" at 11575.39,891.74 h60
  text ".Layer_Name" at 577,-858.49 h60
M11 Gerber Information:
  lines w10: -292,-930.17 6308,-930.17 ; -292,-726.83 6310,-726.83 ; -292,-523.5 -292,-1133.5 3713,-1133.5 6310,-1133.5 6310,-523.5 -291.5,-523.5 -291.5,-1133.5 1284,-1133.5 ; 2173,-1133.5 2173,-523.5 ; 3440,-726.83 3440,-523.5 ; 4280,-726.83 4280,-523.5 ; 4902,-1140 4902,-937.17
  text "ALL ARTWORK VIEWED FROM TOP SIDE" at -228.5,-655.67 h60
  text "BOARD #:" at 2248,-655.67 h60
  text ".PRJ_Number" at 2793.5,-655.67 h60
  text "REV:" at 3638,-655.67 h60
  text ".PCB_Rev" at 3929.5,-655.67 h60
  text "SVN REV:" at 4476,-655.67 h60
  text ".VersionControl_RevNumber" at 4982,-655.67 h60
  text "LAYER NAME =" at -228.5,-858.49 h60
  text "TID #:" at 2248,-859 h60
  text ".TID" at 2793.5,-859 h60
  text "PLOT NAME =" at -228.5,-1064.34 h60
  text ".plot_File_Name" at 577,-1064.34 h60
  text "GENERATED    :" at 2250,-1064.34 h60
  text ".Print_Date" at 3119.5,-1064.34 h60
  text ".Print_Time" at 3848.5,-1064.34 h60
  text "TEXAS INSTRUMENTS" at 5113,-1064.34 h60
M12 Stackup:
  drawing of 295 lines, arcs and shapes, not listed
  text "Layer" at 9821.59,7874.94 h60
  text "Name" at 10231.51,7874.94 h60
  text "Material" at 11171.25,7874.94 h60
  text "Thickness" at 12031.02,7874.94 h60
  text "Constant" at 12680.85,7874.94 h60
  text "Board Layer Stack" at 13250.71,7874.94 h60
  text "Top Overlay" at 10231.51,7754.94 h60
  text "Top Solder" at 10231.51,7634.94 h60
  text "Solder Resist" at 11171.25,7634.94 h60
  text "0.40mil" at 12031.02,7634.94 h60
  text "3.5" at 12680.85,7634.94 h60
  text "1" at 9821.59,7514.94 h60
  text "Top Layer" at 10231.51,7514.94 h60
  text "2.80mil" at 12031.02,7514.94 h60
  text "Dielectric 1" at 10231.51,7394.94 h60
  text "FR-4 High Tg" at 11171.25,7394.94 h60
  text "5.00mil" at 12031.02,7394.94 h60
  text "4.2" at 12680.85,7394.94 h60
  text "2" at 9821.59,7274.94 h60
  text "Signal Layer 1" at 10231.51,7274.94 h60
  text "1.40mil" at 12031.02,7274.94 h60
  text "Dielectric 2" at 10231.51,7154.94 h60
  text "FR-4 High Tg" at 11171.25,7154.94 h60
  text "21.60mil" at 12031.02,7154.94 h60
  text "4.2" at 12680.85,7154.94 h60
  text "3" at 9821.59,7034.94 h60
  text "Signal Layer 2" at 10231.51,7034.94 h60
  text "1.40mil" at 12031.02,7034.94 h60
  text "Dielectric 3" at 10231.51,6914.94 h60
  text "FR-4 High Tg" at 11171.25,6914.94 h60
  text "5.00mil" at 12031.02,6914.94 h60
  text "4.2" at 12680.85,6914.94 h60
  text "4" at 9821.59,6794.94 h60
  text "Bottom Layer" at 10231.51,6794.94 h60
  text "2.80mil" at 12031.02,6794.94 h60
  text "Bottom Solder" at 10231.51,6674.94 h60
  text "Solder Resist" at 11171.25,6674.94 h60
  text "0.40mil" at 12031.02,6674.94 h60
  text "3.5" at 12680.85,6674.94 h60
  text "Bottom Overlay" at 10231.51,6554.94 h60
  text ".Layer_Name" at 577,-858.49 h60
M13 Component Bodies Top:
  text ".Layer_Name" at 577,-858.49 h60
M14 Component Bodies Bottom:
  text ".Layer_Name" at 577,-858.49 h60
M15 Courtyards Top:
  text ".Layer_Name" at 577,-858.49 h60
M16 Courtyards Bottom:
  text ".Layer_Name" at 577,-858.49 h60
Drill Drawing:
  circle w10: c5363.72,2668.68 r27.63
  circle w10: c5363.72,2047.08 r16.58
  circle w10: c5363.72,2047.08 r27.63
  lines w10: 5336.09,2143.78 5391.34,2143.78 5391.34,2199.03 5336.09,2199.03 5336.09,2143.78 ; 5336.09,2295.72 5363.72,2268.1 5391.34,2295.72 5363.72,2323.35 5336.09,2295.72 ; 5336.09,2392.42 5363.72,2406.23 5391.34,2392.42 5377.53,2420.04 5391.34,2447.67 5363.72,2433.86 5336.09,2447.67 5349.9,2420.04 5336.09,2392.42 ; 5336.09,2530.55 5349.9,2530.55 5363.72,2516.74 5377.53,2530.55 5391.34,2530.55 5377.53,2544.36 5391.34,2558.18 5377.53,2558.18 5363.72,2571.99 5349.9,2558.18 5336.09,2558.18 5349.9,2544.36 5336.09,2530.55 ; 5336.09,2820.63 5391.34,2820.63 5363.72,2765.38 5336.09,2820.63 ; 5336.09,2889.7 5391.34,2889.7 5391.34,2944.95 5336.09,2944.95 5336.09,2889.7 ; 5336.09,3027.83 5349.9,3027.83 5363.72,3014.02 5377.53,3027.83 5391.34,3027.83 5377.53,3041.64 5391.34,3055.46 5377.53,3055.46 5363.72,3069.27 5349.9,3055.46 5336.09,3055.46 5349.9,3041.64 5336.09,3027.83 ; 5336.09,3193.59 5391.34,3193.59 5363.72,3138.34 5336.09,3193.59 ; 5336.09,3262.66 5336.09,3276.47 5349.9,3290.28 5336.09,3304.1 5336.09,3317.91 5349.9,3317.91 5363.72,3304.1 5377.53,3317.91 5391.34,3317.91 5391.34,3304.1 5377.53,3290.28 5391.34,3276.47 5391.34,3262.66 5377.53,3262.66 5363.72,3276.47 5349.9,3262.66 5336.09,3262.66 ; 5347.14,2154.83 5380.29,2154.83 5380.29,2187.98 5347.14,2187.98 5347.14,2154.83 ; 5347.14,3033.35 5355.43,3033.35 5363.72,3025.07 5372.01,3033.35 5380.29,3033.35 5372.01,3041.64 5380.29,3049.93 5372.01,3049.93 5363.72,3058.22 5355.43,3049.93 5347.14,3049.93 5355.43,3041.64 5347.14,3033.35 ; 5347.14,3182.54 5380.29,3182.54 5363.72,3149.39 5347.14,3182.54
  lines w12: 5286,1982.16 8517.49,1982.16 ; 5286,3349.68 8517.49,3349.68 ; 5623.86,1857.84 5623.86,3474 ; 5955.86,1857.84 5955.86,3474 ; 6592.43,1857.84 6592.43,3474 ; 6851.57,1857.84 6851.57,3474 ; 7226.72,1857.84 7226.72,3474 ; 7951.05,1857.84 7951.05,3474 ; 5286,1857.84 8517.49,1857.84 8517.49,3474 5286,3474 5286,1857.84
  text "Symbol" at 5360.59,3386.98 h72
  text "Quantity" at 5661.16,3386.98 h72
  text "Finished Hole Size" at 5993.16,3386.98 h72
  text "Plated" at 6629.72,3386.98 h72
  text "Hole Type" at 6888.86,3386.98 h72
  text "Drill Layer Pair" at 7264.02,3386.98 h72
  text "Hole Tolerance" at 7988.35,3386.98 h72
  text "4" at 5661.16,3262.66 h60
  text "7.87mil (0.200mm)" at 5993.16,3262.66 h60
  text "PTH" at 6629.72,3262.66 h60
  text "Round" at 6888.86,3262.66 h60
  text "Top Layer - Bottom Layer" at 7264.02,3262.66 h60
  text "19" at 5661.16,3138.34 h60
  text "8.00mil (0.203mm)" at 5993.16,3138.34 h60
  text "PTH" at 6629.72,3138.34 h60
  text "Round" at 6888.86,3138.34 h60
  text "Top Layer - Bottom Layer" at 7264.02,3138.34 h60
  text "1" at 5661.16,3014.02 h60
  text "11.81mil (0.300mm)" at 5993.16,3014.02 h60
  text "PTH" at 6629.72,3014.02 h60
  text "Round" at 6888.86,3014.02 h60
  text "Top Layer - Bottom Layer" at 7264.02,3014.02 h60
  text "3" at 5661.16,2889.7 h60
  text "40.00mil (1.016mm)" at 5993.16,2889.7 h60
  text "PTH" at 6629.72,2889.7 h60
  text "Round" at 6888.86,2889.7 h60
  text "Top Layer - Bottom Layer" at 7264.02,2889.7 h60
  text "4" at 5661.16,2765.38 h60
  text "45.28mil (1.150mm)" at 5993.16,2765.38 h60
  text "PTH" at 6629.72,2765.38 h60
  text "Round" at 6888.86,2765.38 h60
  text "Top Layer - Bottom Layer" at 7264.02,2765.38 h60
  text "6" at 5661.16,2641.06 h60
  text "59.06mil (1.500mm)" at 5993.16,2641.06 h60
  text "PTH" at 6629.72,2641.06 h60
  text "Round" at 6888.86,2641.06 h60
  text "Top Layer - Bottom Layer" at 7264.02,2641.06 h60
  text "9" at 5661.16,2516.74 h60
  text "62.99mil (1.600mm)" at 5993.16,2516.74 h60
  text "PTH" at 6629.72,2516.74 h60
  text "Round" at 6888.86,2516.74 h60
  text "Top Layer - Bottom Layer" at 7264.02,2516.74 h60
  text "4" at 5661.16,2392.42 h60
  text "63.00mil (1.600mm)" at 5993.16,2392.42 h60
  text "PTH" at 6629.72,2392.42 h60
  text "Round" at 6888.86,2392.42 h60
  text "Top Layer - Bottom Layer" at 7264.02,2392.42 h60
  text "6" at 5661.16,2268.1 h60
  text "39.37mil (1.000mm)" at 5993.16,2268.1 h60
  text "NPTH" at 6629.72,2268.1 h60
  text "Slot" at 6888.86,2268.1 h60
  text "Top Layer - Bottom Layer" at 7264.02,2268.1 h60
  text "2" at 5661.16,2143.78 h60
  text "39.37mil (1.000mm)" at 5993.16,2143.78 h60
  text "NPTH" at 6629.72,2143.78 h60
  text "Slot" at 6888.86,2143.78 h60
  text "Top Layer - Bottom Layer" at 7264.02,2143.78 h60
  text "1" at 5661.16,2019.46 h60
  text "39.37mil (1.000mm)" at 5993.16,2019.46 h60
  text "NPTH" at 6629.72,2019.46 h60
  text "Slot" at 6888.86,2019.46 h60
  text "Top Layer - Bottom Layer" at 7264.02,2019.46 h60
  text "59 Total" at 5661.16,1895.14 h60
  text "Slot definitions :" at 5360.59,1808.11 h60
  text "Routed Path Length" at 5811.31,1808.11 h60
  text "= Calculated from tool start centre position to tool end centre position." at 6351.05,1808.11 h60
  text "Hole Length" at 5811.31,1758.38 h60
  text "= Routed Path Length + Tool Size = Slot length as defined in the PCB layout" at 6151.24,1758.38 h60
  text ".Layer_Name" at 577,-858.49 h60
M17 Embedded Cavity:
  text ".Layer_Name" at 577,-858.49 h60
M18 Embedded Assembly:
  text ".Layer_Name" at 577,-858.49 h60
M19 Embedded Keepout:
  text ".Layer_Name" at 577,-858.49 h60

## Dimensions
0,-400 to 1000,-400 on M2 Board Dimensions
0,0 to 0,1895 on M2 Board Dimensions
0,0 to 3543.31,0 on M2 Board Dimensions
